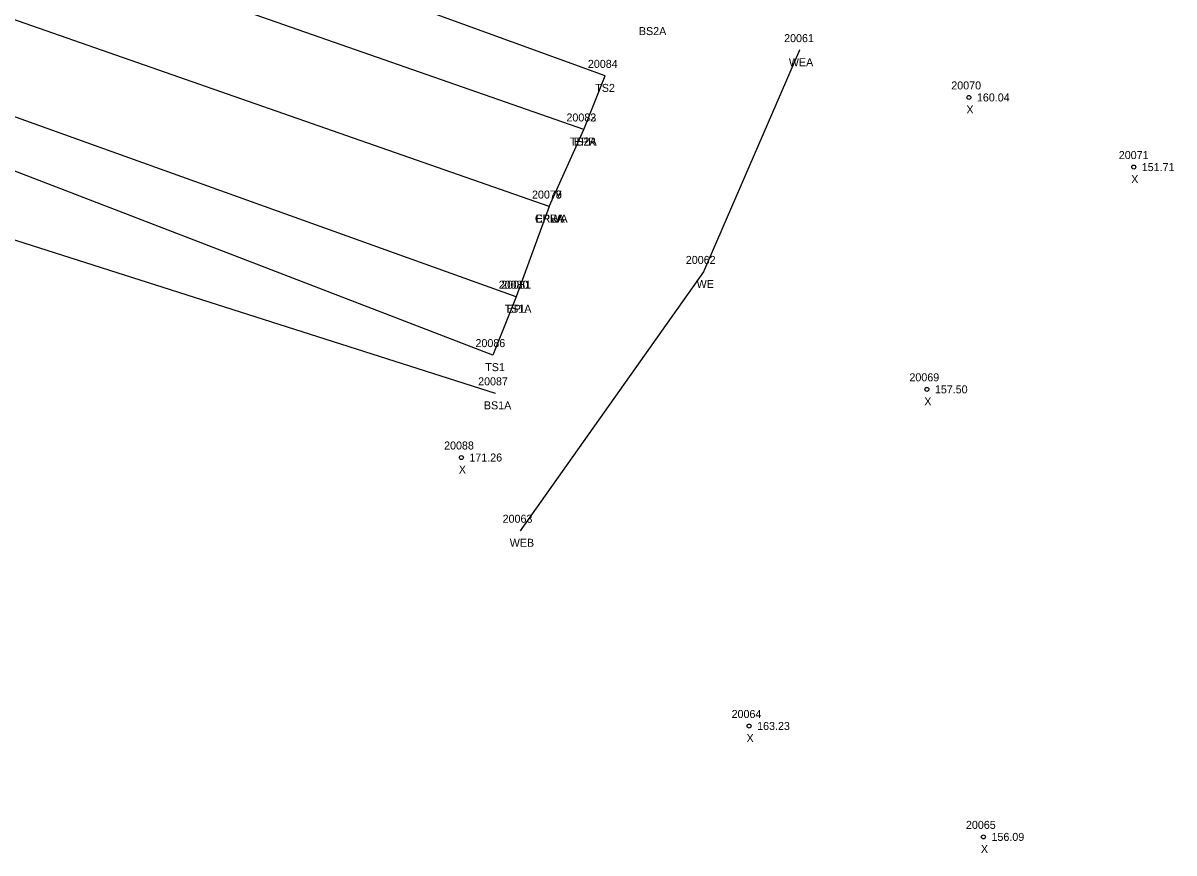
# Model space of a CAD drawing. Extents: x 2054705 to 2055845, y 756616 to 757058.
# Drawn here: x 2055132.6 to 2055276.4, y 756781 to 756884.6 of the extents above; entities that cross this region are included whole.
import ezdxf

# ---------------------------------------------------------------- set-up
doc = ezdxf.new("R2010")
doc.units = 0
for name, color, linetype in [('RD_DTM_BkLn1', 7, 'Continuous'), ('RD_DTM_BkLn2', 7, 'Continuous'), ('RD_EX_H2O', 7, 'Continuous'), ('RD_EX_H2O_txCode', 7, 'Continuous'), ('RD_EX_Road', 7, 'Continuous'), ('RD_EX_Road_txCode', 7, 'Continuous'), ('RD_Sketch8', 7, 'Continuous'), ('RD_SMD_Locator', 7, 'Continuous'), ('RD_SMD_Misc', 7, 'Continuous')]:
    doc.layers.add(name, color=color, linetype=linetype)

msp = doc.modelspace()

# ---------------------------------------------------------------- linework, layer by layer
at = {"layer": 'RD_DTM_BkLn1'}
msp.add_lwpolyline([(2055198.36, 756861.7), (2055105.78, 756894.05), (2055007.93, 756928.48), (2054913.01, 756962.02), (2054814.44, 756996.55), (2054720.09, 757029.92)], dxfattribs=at)
at = {"layer": 'RD_DTM_BkLn2'}
for points in [[(2055202.66, 756871.32), (2055205.34, 756878.01), (2055110.35, 756912.5), (2055013.19, 756941.9), (2054919.26, 756977.81), (2054820.17, 757010.81), (2054725.86, 757045.67)], [(2055194.23, 756850.45), (2055191.32, 756843.16), (2055102.38, 756877.36), (2055003.34, 756913.89), (2054907.82, 756946.94), (2054809.11, 756982.01), (2054715.58, 757014.67)], [(2055191.63, 756838.39), (2055097.99, 756868.2), (2055000.1, 756903.36), (2054903.44, 756936.48), (2054804.9, 756971.5), (2054712.86, 757006.97)]]:
    msp.add_lwpolyline(points, dxfattribs=at)
at = {"layer": 'RD_EX_H2O'}
msp.add_lwpolyline([(2055229.59, 756881.22), (2055217.6, 756853.54), (2055194.71, 756821.24)], dxfattribs=at)
at = {"layer": 'RD_EX_Road'}
for points in [[(2055198.36, 756861.7), (2055202.66, 756871.32), (2055108.14, 756904.32), (2055012.29, 756937.9), (2054917, 756972.03), (2054818.52, 757006.44), (2054723.95, 757039.68)], [(2055198.36, 756861.7), (2055194.23, 756850.45), (2055102.54, 756883.31), (2055004.69, 756917.96), (2054909.06, 756951.44), (2054810.65, 756986.13), (2054717.55, 757018.91)]]:
    msp.add_lwpolyline(points, dxfattribs=at)
at = {"layer": 'RD_SMD_Locator'}
for centre, radius in [((2055229.59, 756881.22), 0.001), ((2055205.34, 756878.01), 0.001), ((2055250.77, 756875.32), 0.25), ((2055202.66, 756871.32), 0.001), ((2055202.66, 756871.32), 0.001), ((2055271.36, 756866.63), 0.25), ((2055198.36, 756861.7), 0.001), ((2055198.36, 756861.7), 0.001), ((2055198.36, 756861.7), 0.001), ((2055217.6, 756853.54), 0.001), ((2055194.23, 756850.45), 0.001), ((2055194.23, 756850.45), 0.001), ((2055191.32, 756843.16), 0.001), ((2055191.63, 756838.39), 0.001), ((2055245.52, 756838.89), 0.25), ((2055187.38, 756830.38), 0.25), ((2055194.71, 756821.24), 0.001), ((2055223.32, 756796.87), 0.25), ((2055252.59, 756783.03), 0.25)]:
    msp.add_circle(centre, radius, dxfattribs=at)

# ---------------------------------------------------------------- texts
at = {"layer": 'RD_EX_H2O_txCode'}
for s, p in [('20061', (2055227.69, 756882.22)), ('WEA', (2055228.28, 756879.22)), ('20062', (2055215.41, 756854.54)), ('WE', (2055216.76, 756851.54)), ('20063', (2055192.53, 756822.24)), ('WEB', (2055193.42, 756819.24))]:
    msp.add_text(s, height=1, dxfattribs=at).set_placement(p)
at = {"layer": 'RD_EX_Road_txCode'}
for s, p in [('20082', (2055200.5, 756872.32)), ('EPR', (2055201.43, 756869.32)), ('20078', (2055196.2, 756862.7)), ('20079', (2055196.2, 756862.7)), ('EPRA', (2055196.64, 756859.7)), ('EPLA', (2055196.67, 756859.7)), ('20080', (2055192.04, 756851.45)), ('EPL', (2055193.03, 756848.45))]:
    msp.add_text(s, height=1, dxfattribs=at).set_placement(p)
at = {"layer": 'RD_Sketch8'}
for s, p in [('20070', (2055248.57, 756876.32)), ('160.04', (2055251.77, 756874.82)), ('X', (2055250.46, 756873.32)), ('20071', (2055269.49, 756867.63)), ('151.71', (2055272.36, 756866.13)), ('X', (2055271.04, 756864.63)), ('20069', (2055243.34, 756839.89)), ('157.50', (2055246.52, 756838.39)), ('X', (2055245.2, 756836.89)), ('20088', (2055185.22, 756831.38)), ('171.26', (2055188.38, 756829.88)), ('X', (2055187.06, 756828.38)), ('20064', (2055221.13, 756797.87)), ('163.23', (2055224.32, 756796.37)), ('X', (2055223, 756794.87)), ('20065', (2055250.4, 756784.03)), ('156.09', (2055253.59, 756782.53)), ('X', (2055252.27, 756781.03))]:
    msp.add_text(s, height=1, dxfattribs=at).set_placement(p)
at = {"layer": 'RD_SMD_Misc'}
for s, p in [('BS2A', (2055209.55, 756883.1)), ('20084', (2055203.18, 756879.01)), ('TS2', (2055204.1, 756876.01)), ('20083', (2055200.5, 756872.32)), ('TS2A', (2055200.93, 756869.32)), ('20077', (2055196.2, 756862.7)), ('CRWA', (2055196.56, 756859.7)), ('20081', (2055192.36, 756851.45)), ('TS1A', (2055192.78, 756848.45)), ('20086', (2055189.14, 756844.16)), ('TS1', (2055190.36, 756841.16)), ('20087', (2055189.47, 756839.39)), ('BS1A', (2055190.19, 756836.39))]:
    msp.add_text(s, height=1, dxfattribs=at).set_placement(p)

doc.saveas('drawing.dxf')
